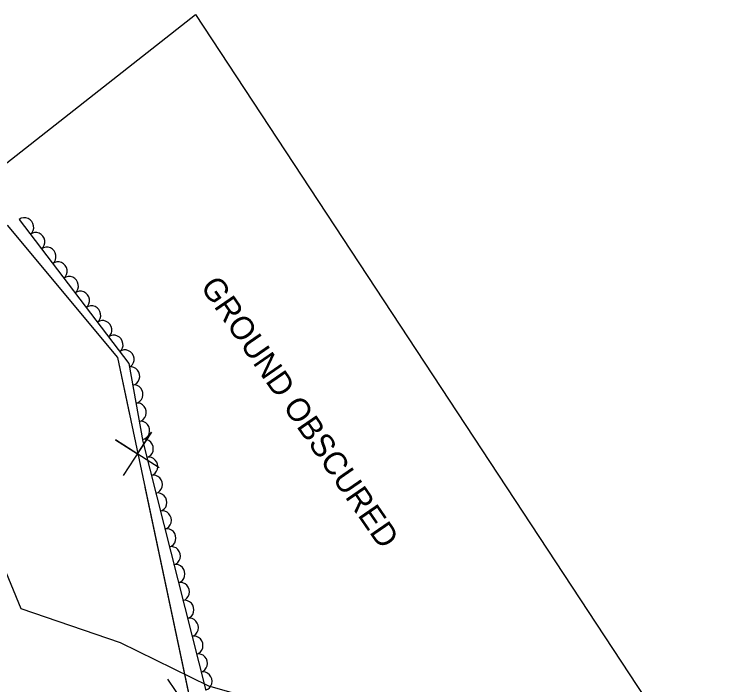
# Model space of a CAD drawing. Extents: x 1746719 to 1766531, y 631721 to 662391.
# Drawn here: x 1759430.8 to 1759587.2, y 642544.3 to 642689.6 of the extents above; entities that cross this region are included whole.
import ezdxf

# ---------------------------------------------------------------- set-up
doc = ezdxf.new("R2010")
doc.units = 0
for name, color, linetype in [('SURVEY - AERIAL SURVEY - Photo Control - Points - Locators', 7, 'Continuous'), ('SURVEY - AERIAL SURVEY - Photo Control with Text', 7, 'Continuous'), ('SURVEY - CENTERLINE - Existing Roads Curve Text', 7, 'Continuous'), ('SURVEY - CENTERLINE - Existing Roads Text', 7, 'Continuous')]:
    doc.layers.add(name, color=color, linetype=linetype)

msp = doc.modelspace()

# ---------------------------------------------------------------- linework, layer by layer
at = {"layer": 'SURVEY - AERIAL SURVEY - Photo Control - Points - Locators'}
msp.add_lwpolyline([(1759470.07, 642689.62), (1759587.17, 642511.63), (1759472.97, 642543.97), (1759453.79, 642553.41), (1759432.21, 642560.75), (1759407.67, 642620.4), (1759399.65, 642634.35), (1759470.07, 642689.62)], dxfattribs=at)
at = {"layer": 'SURVEY - AERIAL SURVEY - Photo Control with Text'}
msp.add_lwpolyline([(1759431.83, 642645.18), (1759455.58, 642613.97), (1759458.62, 642597.05), (1759472.26, 642543.03)], dxfattribs=at)
for centre, major_axis in [((1759433.04, 642643.59), (1.21, -1.59)), ((1759435.46, 642640.4), (1.21, -1.59)), ((1759437.88, 642637.22), (1.21, -1.59)), ((1759440.31, 642634.04), (1.21, -1.59)), ((1759442.73, 642630.85), (1.21, -1.59)), ((1759445.15, 642627.67), (1.21, -1.59)), ((1759447.57, 642624.49), (1.21, -1.59)), ((1759450, 642621.3), (1.21, -1.59)), ((1759452.42, 642618.12), (1.21, -1.59)), ((1759454.84, 642614.94), (1.21, -1.59)), ((1759456.07, 642611.23), (0.35, -1.97)), ((1759456.78, 642607.29), (0.35, -1.97)), ((1759457.49, 642603.36), (0.35, -1.97)), ((1759458.19, 642599.42), (0.35, -1.97)), ((1759459.01, 642595.51), (0.49, -1.94)), ((1759459.99, 642591.63), (0.49, -1.94)), ((1759460.97, 642587.75), (0.49, -1.94)), ((1759461.95, 642583.87), (0.49, -1.94)), ((1759462.93, 642579.99), (0.49, -1.94)), ((1759463.91, 642576.12), (0.49, -1.94)), ((1759464.89, 642572.24), (0.49, -1.94)), ((1759465.86, 642568.36), (0.49, -1.94)), ((1759466.84, 642564.48), (0.49, -1.94)), ((1759467.82, 642560.6), (0.49, -1.94)), ((1759468.8, 642556.72), (0.49, -1.94)), ((1759469.78, 642552.85), (0.49, -1.94)), ((1759470.76, 642548.97), (0.49, -1.94)), ((1759471.74, 642545.09), (0.49, -1.94))]:
    msp.add_ellipse(centre, major_axis=major_axis, ratio=0.940188, start_param=0, end_param=3.141593, dxfattribs=at)
at = {"layer": 'SURVEY - CENTERLINE - Existing Roads Curve Text'}
for points in [[(1759429.21, 642643.93), (1759453.12, 642615.23), (1759469.32, 642538.74)], [(1759429.21, 642643.93), (1759453.12, 642615.23), (1759455.74, 642602.86)], [(1759462.17, 642591.34), (1759452.71, 642597.42), (1759457.45, 642594.33), (1759460.53, 642599.07), (1759454.34, 642589.69)], [(1759459.08, 642587.11), (1759468.69, 642541.72)]]:
    msp.add_lwpolyline(points, dxfattribs=at)
at = {"layer": 'SURVEY - CENTERLINE - Existing Roads Text'}
msp.add_line((1759472.78, 642532.52), (1759464.08, 642545.48), dxfattribs=at)

# ---------------------------------------------------------------- texts
at = {"layer": 'SURVEY - AERIAL SURVEY - Photo Control - Points - Locators'}
msp.add_text('GROUND OBSCURED', height=5, rotation=304.5444, dxfattribs=at).set_placement((1759470.97, 642630.62))

doc.saveas('drawing.dxf')
